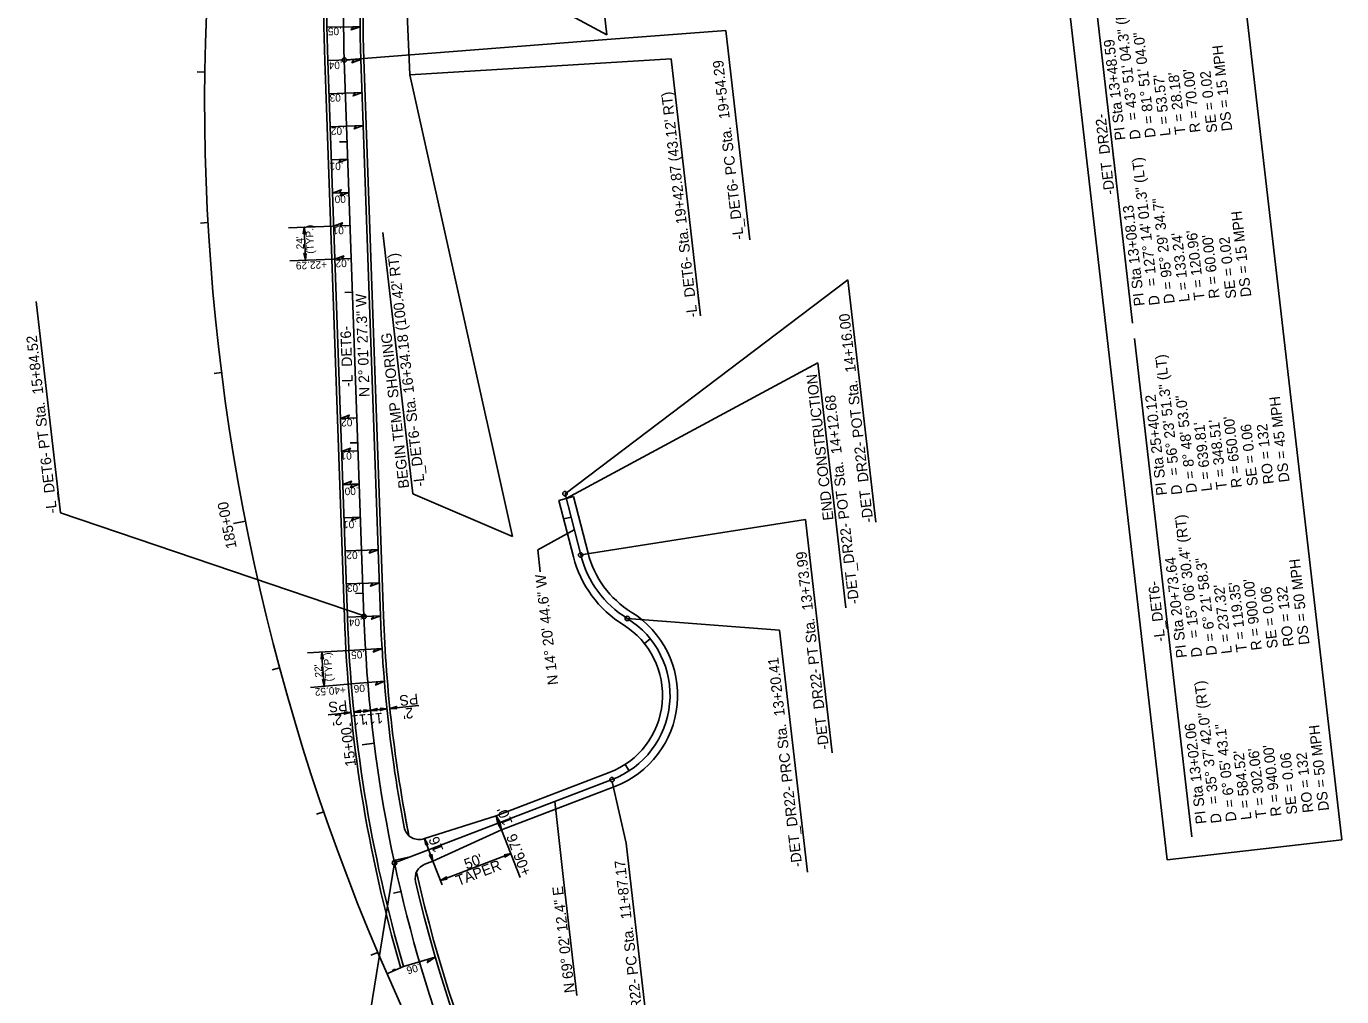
# Model space of a CAD drawing. Extents: x 473658 to 481584, y 489119 to 506230.
# Drawn here: x 474403 to 475276, y 503679 to 504324 of the extents above; entities that cross this region are included whole.
import ezdxf

# ---------------------------------------------------------------- set-up
doc = ezdxf.new("R2010")
doc.units = 0
for name, color, linetype in [('Exist Horizontal Alignment', 7, 'Continuous'), ('Exist Structure Minor Pipes CMP 60 Inch', 7, 'Continuous'), ('Prop Dimension', 7, 'Continuous'), ('Prop EOT', 7, 'Continuous'), ('Prop Grid Mask', 7, 'Continuous'), ('Prop Horizontal Alignment', 7, 'Continuous'), ('Prop Horizontal Alignment Curve and Spiral Data', 7, 'Continuous'), ('Prop Horizontal Alignment Direction Label', 7, 'Continuous'), ('Prop Horizontal Alignment Station Label', 7, 'Continuous'), ('Prop Horizontal Alignment Tick Label', 7, 'Continuous'), ('Prop Horizontal Alignment Tick Large', 7, 'Continuous'), ('Prop Horizontal Alignment Tick Small', 7, 'Continuous'), ('Prop Paved Shoulder', 7, 'Continuous'), ('Prop Superelevation  Arrow CELL', 7, 'Continuous'), ('Prop Superelevation Label', 7, 'Continuous'), ('Scratch_Level_5', 7, 'Continuous'), ('Scratch_Level_6', 7, 'Continuous'), ('Sheet Profile Grid Major CELL', 7, 'Continuous')]:
    doc.layers.add(name, color=color, linetype=linetype)

msp = doc.modelspace()

# ---------------------------------------------------------------- linework, layer by layer
at = {"layer": 'Exist Horizontal Alignment'}
for points in [[(474715.6, 503794.74), (474714.72, 503799.22), (474717.08, 503795.28), (474716.13, 503795.53)], [(474717.41, 503794.36), (474718.29, 503789.88), (474715.93, 503793.82), (474716.88, 503793.57)], [(474667.92, 503779.69), (474667.04, 503784.17), (474669.4, 503780.23), (474668.45, 503780.48)], [(474671.88, 503773.71), (474672.76, 503769.23), (474670.4, 503773.17), (474671.35, 503772.91)], [(474719.94, 503773.35), (474724.42, 503774.23), (474720.48, 503771.87), (474720.73, 503772.82)], [(474682.21, 503757.23), (474677.73, 503756.35), (474681.67, 503758.71), (474681.42, 503757.76)]]:
    msp.add_lwpolyline(points, close=True, dxfattribs=at)
at = {"layer": 'Exist Structure Minor Pipes CMP 60 Inch'}
msp.add_lwpolyline([(474725.53, 503984.81), (474657.37, 504291.29), (474655.39, 504336.72), (474656.22, 504389)], dxfattribs=at)
at = {"layer": 'Prop Dimension'}
for p, q in [((474618.28, 503867.98), (474603.17, 503866.43)), ((474642.16, 503870.42), (474620.27, 503868.18)), ((474663.39, 503872.59), (474644.15, 503870.62))]:
    msp.add_line(p, q, dxfattribs=at)
for points in [[(474613.73, 503868.29), (474618.28, 503867.98), (474613.86, 503866.72), (474614.35, 503867.58)], [(474624.83, 503867.87), (474620.27, 503868.18), (474624.69, 503869.44), (474624.2, 503868.58)], [(474626.66, 503869.61), (474631.21, 503869.3), (474626.79, 503868.04), (474627.28, 503868.9)], [(474635.77, 503868.99), (474631.21, 503869.3), (474635.63, 503870.56), (474635.14, 503869.7)], [(474637.6, 503870.73), (474642.16, 503870.42), (474637.74, 503869.16), (474638.23, 503870.02)], [(474648.7, 503870.31), (474644.15, 503870.62), (474648.57, 503871.88), (474648.08, 503871.02)]]:
    msp.add_lwpolyline(points, close=True, dxfattribs=at)
at = {"layer": 'Prop EOT'}
for p, q in [((474615.94, 503931.25), (474602.88, 504300.79)), ((474637.93, 503932.03), (474624.86, 504301.57)), ((474766.08, 504011.22), (474756.39, 504008.74)), ((474765.98, 503971.25), (474756.39, 504008.74)), ((474775.67, 503973.73), (474766.08, 504011.22)), ((474714.72, 503799.22), (474789.81, 503827.99)), ((474718.29, 503789.88), (474793.39, 503818.65)), ((474667.04, 503784.17), (474714.72, 503799.22)), ((474672.76, 503769.23), (474718.29, 503789.88)), ((474667.39, 503767.17), (474672.76, 503769.23))]:
    msp.add_line(p, q, dxfattribs=at)
for centre, radius, start, end in [((475513.31, 504332.97), 911, 166.91582, 182.02426), ((475513.31, 504332.97), 889, 166.91582, 182.02426), ((474838.64, 503989.83), 65, 194.34572, 238.19692), ((474838.64, 503989.83), 75, 194.34572, 238.19692), ((475566.35, 503964.84), 951, 182.02426, 196.21578), ((475566.35, 503964.84), 929, 182.02426, 188.23567), ((474770.13, 503879.35), 65, 290.96322, 58.19692), ((474770.13, 503879.35), 55, 290.96322, 58.19692), ((475566.35, 503964.84), 929, 188.23567, 190.74507), ((474663.46, 503793.51), 10, 190.74507, 290.96322), ((474670.97, 503757.83), 10, 110.96322, 193.01816), ((475566.35, 503964.84), 929, 193.01816, 217.6526)]:
    msp.add_arc(centre, radius, start, end, dxfattribs=at)
at = {"layer": 'Prop Grid Mask'}
msp.add_lwpolyline([(475160.21, 503770.12), (475092.92, 504355.81), (475208.66, 504369.11), (475275.95, 503783.42)], close=True, dxfattribs=at)
at = {"layer": 'Prop Horizontal Alignment'}
for p, q in [((474626.93, 503931.64), (474613.87, 504301.18)), ((474770.82, 503972.49), (474760.42, 504013.19)), ((474647.19, 503768), (474791.6, 503823.32))]:
    msp.add_line(p, q, dxfattribs=at)
for centre, radius, start, end in [((475513.31, 504332.97), 900, 166.91582, 182.02426), ((475966.17, 504273.33), 1445, 176.96875, 223.37358), ((474838.64, 503989.83), 70, 194.34572, 238.19692), ((475566.35, 503964.84), 940, 182.02426, 217.6526), ((474770.13, 503879.35), 60, 290.96322, 58.19692)]:
    msp.add_arc(centre, radius, start, end, dxfattribs=at)
at = {"layer": 'Prop Horizontal Alignment Curve and Spiral Data'}
msp.add_line((475137.17, 504126.47), (475111.81, 504347.27), dxfattribs=at)
at = {"layer": 'Prop Horizontal Alignment Station Label'}
for p, q in [((474788.26, 504317.97), (474768.41, 504491.44)), ((474788.26, 504317.97), (474656.22, 504389)), ((474615.37, 504301.23), (474788.13, 504314.69)), ((474788.13, 504314.69), (474867.12, 504320.85)), ((474867.12, 504320.85), (474883.16, 504181.74)), ((474830.88, 504302.01), (474657.37, 504291.29)), ((474850.42, 504131.27), (474830.88, 504302.01)), ((475124.45, 504236.83), (475137.17, 504126.47)), ((474639.41, 504186.58), (474659.42, 504012.98)), ((474760.42, 504013.19), (474948.23, 504155.29)), ((474966.73, 503994.27), (474948.23, 504155.29)), ((474409.34, 504140.82), (474425.52, 504000.5)), ((475138.34, 504116.34), (475176.51, 503785.31)), ((474928.22, 504100.01), (474761.24, 504009.98)), ((474946.91, 503937.31), (474928.22, 504100.01)), ((474725.53, 503984.81), (474659.42, 504012.98)), ((474628.43, 503931.69), (474425.52, 504000.5)), ((474770.82, 503972.49), (474920.04, 503995.96)), ((474937.82, 503841.15), (474920.04, 503995.96)), ((474742.25, 503975.8), (474766.56, 503989.16)), ((474743.93, 503961.21), (474742.25, 503975.8)), ((474801.75, 503930.34), (474902.83, 503922.6)), ((474921.3, 503761.82), (474902.83, 503922.6)), ((474801.03, 503781.12), (474791.6, 503821.82)), ((474759.7, 503754.89), (474753.61, 503808.77)), ((474817.62, 503636.69), (474801.03, 503781.12)), ((474631.17, 503669.72), (474647.19, 503768)), ((474768.32, 503679.89), (474759.7, 503754.89))]:
    msp.add_line(p, q, dxfattribs=at)
for centre in [(474613.87, 504301.18), (474760.42, 504013.19), (474770.82, 503972.49), (474626.93, 503931.64), (474626.93, 503931.64), (474626.93, 503931.64), (474626.93, 503931.64), (474801.75, 503930.34), (474791.6, 503823.32), (474647.19, 503768)]:
    msp.add_circle(centre, 1.5, dxfattribs=at)
at = {"layer": 'Prop Horizontal Alignment Tick Large'}
for p, q in [((474548.25, 503994.91), (474540.4, 503993.36)), ((474633.71, 503847.42), (474625.77, 503846.42))]:
    msp.add_line(p, q, dxfattribs=at)
at = {"layer": 'Prop Horizontal Alignment Tick Small'}
for p, q in [((474521.31, 504293.15), (474516.31, 504293.22)), ((474615.79, 504246.92), (474610.79, 504246.74)), ((474523.39, 504193.19), (474518.4, 504192.92)), ((474619.32, 504146.98), (474614.32, 504146.81)), ((474532.39, 504093.62), (474527.43, 504093)), ((474622.85, 504047.05), (474617.86, 504046.87)), ((474764.38, 503997.69), (474759.54, 503996.45)), ((474626.39, 503947.11), (474621.39, 503946.93)), ((474816.95, 503916.87), (474813.05, 503913.74)), ((474570.89, 503897.52), (474566.07, 503896.22)), ((474803, 503829.15), (474800.26, 503833.34)), ((474600.22, 503801.94), (474595.49, 503800.31)), ((474651.45, 503749.05), (474646.58, 503747.9)), ((474636.09, 503708.62), (474631.48, 503706.66))]:
    msp.add_line(p, q, dxfattribs=at)
at = {"layer": 'Prop Paved Shoulder'}
for p, q in [((474613.94, 503931.18), (474600.88, 504300.72)), ((474639.92, 503932.1), (474626.86, 504301.64))]:
    msp.add_line(p, q, dxfattribs=at)
for centre, radius, start, end in [((475513.31, 504332.97), 913, 166.91582, 182.02426), ((475513.31, 504332.97), 887, 166.91582, 182.02426), ((475566.35, 503964.84), 953, 182.02426, 196.21578), ((475566.35, 503964.84), 927, 182.02426, 191.11753), ((475566.35, 503964.84), 927, 189.67775, 191.11753), ((475566.35, 503964.84), 927, 192.6457, 215.63836)]:
    msp.add_arc(centre, radius, start, end, dxfattribs=at)
at = {"layer": 'Prop Superelevation  Arrow CELL'}
for points in [[(474624.36, 504323.29), (474618.38, 504321.23), (474619.74, 504323.24)], [(474624.87, 504301.56), (474618.94, 504299.34), (474620.24, 504301.39)], [(474625.64, 504279.58), (474619.72, 504277.37), (474621.02, 504279.42)], [(474626.42, 504257.59), (474620.49, 504255.38), (474621.8, 504257.43)], [(474616.2, 504235.22), (474610.28, 504233.01), (474611.58, 504235.05)], [(474605.99, 504212.84), (474611.91, 504215.05), (474610.61, 504213.01)], [(474616.98, 504213.23), (474611.05, 504211.02), (474612.36, 504213.07)], [(474606.76, 504190.86), (474612.69, 504193.07), (474611.39, 504191.02)], [(474586.65, 504185.64), (474587.27, 504190.17), (474588.23, 504185.67), (474587.41, 504186.22)], [(474588.66, 504172.71), (474588.04, 504168.18), (474587.08, 504172.68), (474587.9, 504172.13)], [(474607.54, 504168.87), (474613.47, 504171.08), (474612.16, 504169.03)], [(474611.28, 504063.17), (474617.2, 504065.38), (474615.9, 504063.33)], [(474612.05, 504041.18), (474617.98, 504043.39), (474616.68, 504041.34)], [(474612.83, 504019.19), (474618.76, 504021.41), (474617.45, 504019.36)], [(474623.82, 504019.58), (474617.9, 504017.37), (474619.2, 504019.42)], [(474624.6, 503997.6), (474618.68, 503995.39), (474619.98, 503997.43)], [(474636.37, 503976), (474630.45, 503973.79), (474631.75, 503975.84)], [(474637.15, 503954.01), (474631.22, 503951.8), (474632.53, 503953.85)], [(474637.93, 503932.03), (474632, 503929.82), (474633.3, 503931.86)], [(474598.5, 503903.41), (474598.94, 503907.96), (474600.07, 503903.5), (474599.23, 503904.02)], [(474638.95, 503910.31), (474633.08, 503907.96), (474634.33, 503910.04)], [(474601.02, 503889.88), (474600.58, 503885.34), (474599.45, 503889.79), (474600.29, 503889.27)], [(474640.48, 503888.62), (474634.66, 503886.13), (474635.87, 503888.24)], [(474674.3, 503705.41), (474669.1, 503701.82), (474669.86, 503704.12)]]:
    msp.add_lwpolyline(points, close=True, dxfattribs=at)
at = {"layer": 'Prop Superelevation Label'}
for p, q in [((474602.36, 504323.05), (474624.36, 504323.29)), ((474602.88, 504300.78), (474624.87, 504301.56)), ((474603.66, 504278.8), (474625.64, 504279.58)), ((474604.43, 504256.82), (474626.42, 504257.59)), ((474605.21, 504234.83), (474616.2, 504235.22)), ((474605.99, 504212.84), (474616.98, 504213.23)), ((474576.95, 504189.8), (474617.76, 504191.25)), ((474588.04, 504168.18), (474587.27, 504190.17)), ((474577.73, 504167.82), (474618.53, 504169.26)), ((474611.28, 504063.17), (474622.27, 504063.56)), ((474612.05, 504041.18), (474623.05, 504041.57)), ((474612.83, 504019.19), (474623.82, 504019.58)), ((474613.61, 503997.21), (474624.6, 503997.6)), ((474614.39, 503975.22), (474636.37, 503976)), ((474615.16, 503953.24), (474637.15, 503954.01)), ((474615.94, 503931.25), (474637.93, 503932.03)), ((474589.46, 503907.4), (474616.99, 503909.02)), ((474616.99, 503909.02), (474638.95, 503910.31)), ((474591.39, 503884.58), (474618.55, 503886.82)), ((474618.55, 503886.82), (474640.48, 503888.62)), ((474653.18, 503699.27), (474674.3, 503705.41))]:
    msp.add_line(p, q, dxfattribs=at)
msp.add_arc((475566.24, 503966.9), 969.1, 183.48721, 184.82812, dxfattribs=at)
at = {"layer": 'Scratch_Level_5'}
msp.add_line((474657.59, 503771.98), (474646.83, 503769.7), dxfattribs=at)
at = {"layer": 'Scratch_Level_6'}
for p, q in [((474602.36, 504323.05), (474624.36, 504323.29)), ((474602.88, 504300.79), (474624.86, 504301.57)), ((474603.66, 504278.8), (474625.64, 504279.58)), ((474604.43, 504256.82), (474626.42, 504257.59)), ((474605.21, 504234.83), (474616.2, 504235.22)), ((474605.99, 504212.84), (474616.98, 504213.23)), ((474606.76, 504190.86), (474617.76, 504191.25)), ((474607.54, 504168.87), (474618.53, 504169.26)), ((474611.28, 504063.17), (474622.27, 504063.56)), ((474612.05, 504041.18), (474623.05, 504041.57)), ((474612.83, 504019.19), (474623.82, 504019.58)), ((474613.61, 503997.21), (474624.6, 503997.6)), ((474614.39, 503975.22), (474636.37, 503976)), ((474615.16, 503953.24), (474637.15, 503954.01)), ((474615.94, 503931.25), (474637.93, 503932.03)), ((474616.99, 503909.02), (474638.95, 503910.31)), ((474618.55, 503886.82), (474640.48, 503888.62)), ((474653.18, 503699.27), (474642.19, 503694.46)), ((474645.77, 503696.54), (474647.98, 503697.48))]:
    msp.add_line(p, q, dxfattribs=at)
msp.add_lwpolyline([(474647.98, 503697.48), (474647.5, 503697.06), (474647.55, 503697.3)], close=True, dxfattribs=at)
at = {"layer": 'Sheet Profile Grid Major CELL'}
for p, q in [((474718.29, 503789.88), (474714.72, 503799.22)), ((474730.54, 503758.22), (474718.29, 503789.88)), ((474672.76, 503769.23), (474667.04, 503784.17)), ((474677.73, 503756.35), (474724.42, 503774.23)), ((474678.84, 503753.36), (474672.76, 503769.23))]:
    msp.add_line(p, q, dxfattribs=at)

# ---------------------------------------------------------------- texts
at = {"layer": 'Prop Dimension'}
for s, p in [('PS', (474662.59, 503880.42)), ('PS', (474615.56, 503876.04)), ("11'", (474639.25, 503867.83)), ("2'", (474659.33, 503871.17)), ("2'", (474612.29, 503866.78)), ("11'", (474628.5, 503866.96))]:
    msp.add_text(s, height=7, rotation=185.83375, dxfattribs=at).set_placement(p)
at = {"layer": 'Prop Horizontal Alignment Curve and Spiral Data'}
for s, rotation, p in [('= 43%%d 51\' 04.3" (RT)', 96.55384, (475140.8, 504261.49)), ('PI Sta 13+48.59', 96.55384, (475132.55, 504248.29)), ('D = 81%%d 51\' 04.0"', 96.55384, (475152.5, 504249.9)), ('DS = 15 MPH', 96.55384, (475203.39, 504254.33)), ("L = 53.57'", 96.55384, (475162.43, 504251.04)), ("T = 28.18'", 96.55384, (475172.37, 504252.18)), ("R = 70.00'", 96.55384, (475182.3, 504253.33)), ('SE = 0.02', 96.55384, (475193.46, 504253.19)), ('-DET_DR22-', 96.55384, (475125.3, 504212.12)), ('D', 96.55384, (475142.56, 504248.76)), ('= 127%%d 14\' 01.3" (LT)', 96.55384, (475153.45, 504151.37)), ('D = 95%%d 29\' 34.7"', 96.55384, (475165.15, 504139.78)), ('PI Sta 13+08.13', 96.55384, (475145.2, 504138.17)), ('DS = 15 MPH', 96.55384, (475216.04, 504144.21)), ("L = 133.24'", 96.55384, (475175.08, 504140.92)), ("T = 120.96'", 96.55384, (475185.02, 504142.07)), ("R = 60.00'", 96.55384, (475194.95, 504143.21)), ('SE = 0.02', 96.55384, (475206.11, 504143.07)), ('D', 96.55384, (475155.21, 504138.64)), ('= 56%%d 23\' 51.3" (LT)', 96.57729, (475168.29, 504025.62)), ('PI Sta 25+40.12', 96.57729, (475160.04, 504012.41)), ('D = 8%%d 48\' 53.0"', 96.57729, (475179.98, 504014.03)), ('DS = 45 MPH', 96.57729, (475241.39, 504021.11)), ("L = 639.81'", 96.57729, (475189.92, 504015.17)), ("T = 348.51'", 96.57729, (475199.85, 504016.32)), ("R = 650.00'", 96.57729, (475209.79, 504017.47)), ('RO = 132', 96.57729, (475231, 504019.91)), ('SE = 0.06', 96.57729, (475220.39, 504018.69)), ('D', 96.57729, (475170.05, 504012.88)), ('= 15%%d 06\' 30.4" (RT)', 96.57729, (475181.51, 503917.72)), ('PI Sta 20+73.64', 96.57729, (475173.26, 503904.51)), ('D = 6%%d 21\' 58.3"', 96.57729, (475193.21, 503906.13)), ('DS = 50 MPH', 96.57729, (475254.62, 503913.21)), ("R = 900.00'", 96.57729, (475223.01, 503909.57)), ("L = 237.32'", 96.57729, (475203.14, 503907.28)), ("T = 119.35'", 96.57729, (475213.08, 503908.42)), ('SE = 0.06', 96.57729, (475233.62, 503910.79)), ('RO = 132', 96.57729, (475244.22, 503912.01)), ('D', 96.57729, (475183.28, 503904.99)), ('= 35%%d 37\' 42.0" (RT)', 96.57729, (475194.47, 503807.45)), ('PI Sta 13+02.06', 96.57729, (475186.23, 503794.24)), ('D = 6%%d 05\' 43.1"', 96.57729, (475206.17, 503795.86)), ('DS = 50 MPH', 96.57729, (475267.58, 503802.94)), ("L = 584.52'", 96.57729, (475216.11, 503797.01)), ("T = 302.06'", 96.57729, (475226.04, 503798.15)), ("R = 940.00'", 96.57729, (475235.98, 503799.3)), ('RO = 132', 96.57729, (475257.19, 503801.74)), ('SE = 0.06', 96.57729, (475246.58, 503800.52)), ('D', 96.57729, (475196.24, 503794.72))]:
    msp.add_text(s, height=7, rotation=rotation, dxfattribs=at).set_placement(p)
at = {"layer": 'Prop Horizontal Alignment Direction Label'}
for s, rotation, p in [('N 2%%d 01\' 27.3" W', 92.02426, (474630.78, 504077.48)), ('-L_DET6-', 92.02426, (474619.6, 504084.06)), ('N 14%%d 20\' 44.6" W', 96.55384, (474755.93, 503886.55)), ('N 69%%d 02\' 12.4" E', 96.55384, (474766.99, 503682.07))]:
    msp.add_text(s, height=7, rotation=rotation, dxfattribs=at).set_placement(p)
at = {"layer": 'Prop Horizontal Alignment Station Label'}
for s, rotation, p in [('-L_DET6- PC Sta.  19+54.29', 96.57729, (474879.04, 504182.26)), ("-L_DET6- Sta. 19+42.87 (43.12' RT)", 96.57729, (474848.42, 504130.58)), ("-L_DET6- Sta. 16+34.18 (100.42' RT)", 96.57729, (474667.42, 504018.28)), ('-DET_DR22- POT Sta.  14+16.00', 96.55384, (474965.06, 503994.36)), ('-L_DET6- PT Sta.  15+84.52', 96.57729, (474423.29, 504000.54)), ('BEGIN TEMP SHORING', 96.57729, (474656.99, 504017.08)), ('END CONSTRUCTION', 96.55384, (474938.67, 503995.82)), ('-DET_DR22- POT Sta.  14+12.68', 96.55384, (474955.62, 503940.25)), ('-DET_DR22- PT Sta.  13+73.99', 96.55384, (474935.67, 503843.61)), ('-L_DET6-', 96.57729, (475158.89, 503915.16)), ('-DET_DR22- PRC Sta.  13+20.41', 96.55384, (474917.91, 503765.56)), ('-DET_DR22- PC Sta.  11+87.17', 96.55384, (474815.37, 503637.59))]:
    msp.add_text(s, height=7, rotation=rotation, dxfattribs=at).set_placement(p)
at = {"layer": 'Prop Horizontal Alignment Tick Label'}
for s, rotation, p in [('185+00', 101.10944, (474542.51, 503977.43)), ('15+00', 97.17612, (474621.73, 503832.42))]:
    msp.add_text(s, height=7, rotation=rotation, dxfattribs=at).set_placement(p)
at = {"layer": 'Prop Superelevation Label'}
for s, rotation, p in [('.05', 180.62368, (474612.24, 504322.72)), ('.04', 182.02426, (474612.73, 504300.26)), ('.03', 182.02426, (474613.35, 504278.71)), ('.02', 182.02426, (474614.17, 504256.65)), ('.01', 182.02426, (474613.32, 504233.2)), ('.00', 182.02426, (474616.68, 504211.42)), ('(TYP.)', 92.02426, (474593.8, 504172.6)), ('.01', 182.02426, (474615.34, 504190.62)), ("24'", 92.02426, (474587.13, 504175.54)), ('+22.29', 182.02426, (474602.31, 504167.76)), ('.02', 182.02426, (474617.28, 504168.77)), ('.02', 182.02426, (474621.01, 504063.08)), ('.01', 182.02426, (474620.61, 504040.93)), ('.00', 182.02426, (474623.33, 504017.47)), ('.01', 182.02426, (474622.26, 503995.38)), ('.02', 182.02426, (474624.5, 503974.98)), ('.03', 182.02426, (474624.82, 503953.18)), ('.04', 182.02438, (474626.08, 503930.37)), ('(TYP.)', 94.26218, (474606.28, 503888.66)), ('.05', 183.36534, (474627.58, 503909)), ("22'", 94.26218, (474599.51, 503891.33)), ('+40.52', 184.01837, (474614.74, 503885.36)), ('.06', 184.70631, (474629.21, 503886.74)), ('.06', 196.21578, (474663.64, 503701.32))]:
    msp.add_text(s, height=5, rotation=rotation, dxfattribs=at).set_placement(p)
at = {"layer": 'Scratch_Level_6'}
msp.add_text('.06', height=0.5, rotation=202.9087, dxfattribs=at).set_placement((474647.41, 503698))
at = {"layer": 'Sheet Profile Grid Major CELL'}
for s, rotation, p in [("10'", 110.96322, (474725.75, 503794.52)), ("16'", 110.96322, (474679.85, 503776.56)), ('+06.76', 111.13721, (474738.13, 503761.16)), ("50'", 20.96322, (474695.08, 503763.54)), ('TAPER', 20.96322, (474689.6, 503752.6))]:
    msp.add_text(s, height=7, rotation=rotation, dxfattribs=at).set_placement(p)

doc.saveas('drawing.dxf')
